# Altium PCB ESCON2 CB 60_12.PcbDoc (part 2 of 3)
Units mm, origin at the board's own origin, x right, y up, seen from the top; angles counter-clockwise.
Board outline 65.5 x 41 mm, 8 copper layers (Top Side, Mid Layer 1, Mid Layer 2, Mid Layer 3, Mid Layer 4, Mid Layer 5, Mid Layer 6, Bottom Side), stack 1.555 mm thick; 142 components, 77 nets, 455 pads, 2194 vias.
Unrouted connection lines stored in the file: 71.
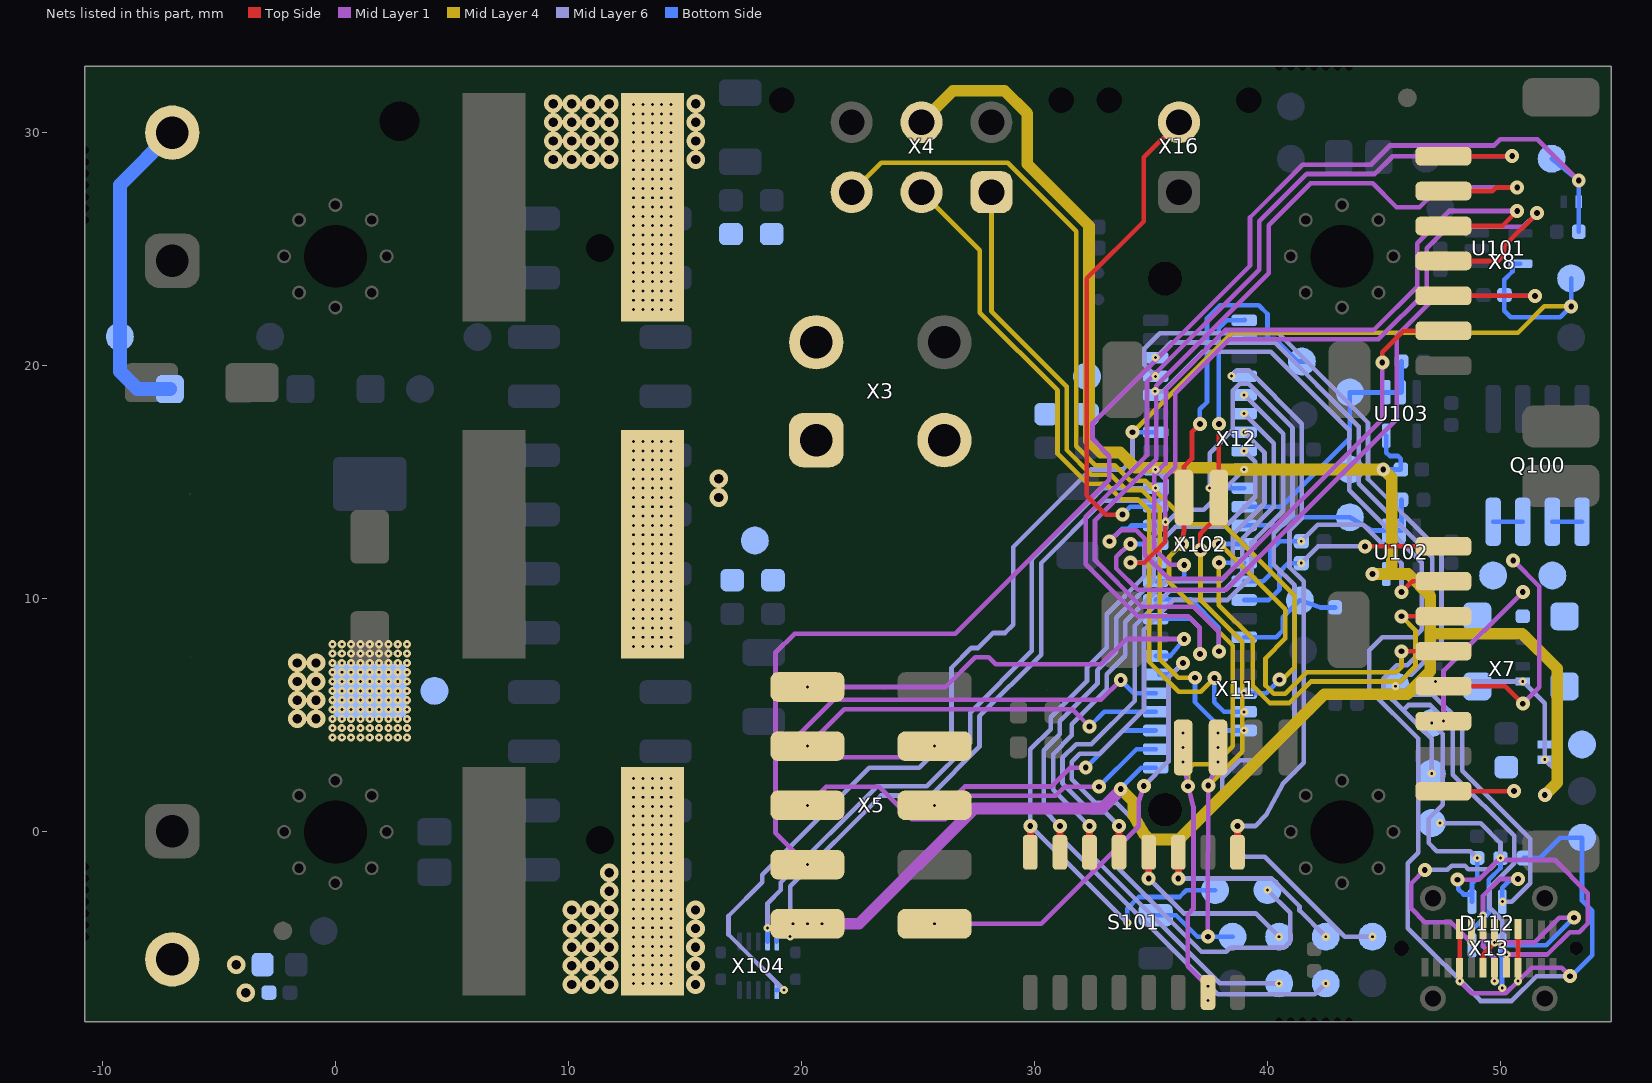
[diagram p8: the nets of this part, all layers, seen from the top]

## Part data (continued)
C112 C116 C122 C123 C124: library part CMP-001306-1, "100nF X7R >=50V 20%", Case=0402, Case (Metric)=1005, Dielectric=X7R, Manufacturer=X, Max Operating Temperature=125°C, Maximum Working Voltage=50V, Min Operating Temperature=-55°C, Part Number="Ceramic, 0402, 100nF, 20%, >{}50V, X7R, @, Soft Termination: N, -55°C to 125°C", Tolerance=20%
C113 C114 C115: library part CMP-001012-4, "220pF C0G/NP0/X7R >=100V 20%", Case=0603, Case (Metric)=1608, Dielectric=C0G/NP0/X7R, Manufacturer=X, Max Operating Temperature=125°C, Maximum Working Voltage=100V, Min Operating Temperature=-55°C, Part Number="Ceramic, 0603, 220pF, 20%, >{}100V, C0G/NP0/X7R, @, Soft Termination: N, -55°C to 125°C", Tolerance=20%
C119 C126: library part CMP-000703-3, "100nF X7R >=100V 20%", Case=0603, Case (Metric)=1608, Dielectric=X7R, Manufacturer=X, Max Operating Temperature=125°C, Maximum Working Voltage=100V, Min Operating Temperature=-55°C, Part Number="Ceramic, 0603, 100nF, 20%, >{}100V, X7R, @, Soft Termination: N, -55°C to 125°C", Tolerance=20%
C125: library part CMP-002520-1, "1nF C0G/NP0 >=100V 10%", Case=0402, Case (Metric)=1005, Dielectric=C0G/NP0, Max Operating Temperature=125°C, Maximum Working Voltage=100V, Min Operating Temperature=-55°C, Part Number="Ceramic, 0402, 1nF, 10%, >{}100V, C0G/NP0, @, Soft Termination: N, -55°C to 125°C", Tolerance=10%
D101 D104: library part CMP-001103-4, "Transient Voltage Suppressor Diode, 60V V(RWM), Unidirectional, 400W, 1 Element, DO-214AC", Breakdown Voltage=66.7V, Case=DO-214AC, Clamping Voltage=96.8V, Manufacturer=X, Max Operating Temperature=150°C, Min Operating Temperature=-55°C
D102 D103 D110 D111: library part CMP-000633-9, "Schottky Diode, >=90V, >=1A, SOD-123FL/SOD-123W", Case="Sub SMA; SOD-123FL", Manufacturer="Taiwan Semiconductor", Max Operating Temperature=150°C, Min Operating Temperature=-55°C, Reverse Voltage=90V, RMS Current=1A
D106: library part CMP-001106-5, "Transient Voltage Suppressor Diode, 12V V(RWM), Bidirectional, 100W, 1 Element, SOD-882/DFN1006", Breakdown Voltage=13V, Case="SOD-882; DFN1006", Manufacturer=Diodes, Max Operating Temperature=125°C, Min Operating Temperature=-40°C
D107 D108 D109: library part CMP-000606-13, "Diode Switching, >=70V, >=150mA, SOD882/DFN1006/0402/SOD-923F", Case="SOD882 / DFN1006 / 0402 / SOD-923F", Manufacturer=MCC, Max Operating Temperature=125°C, Min Operating Temperature=-40°C, Reverse Voltage=70V, RMS Current=150mA
D112: library part CMP-000635-10, "Transient Voltage Suppressor Diode, 4-Line, 5V V(RWM), Unidirectional, 30W, 4 Element , SOT353/SC-88A", Breakdown Voltage=6.8V, Case="SOT353; SC-88A; SOT323-5L", Clamping Voltage=12V, Manufacturer=Nexperia, Max Breakdown Voltage=7.14V, Max Junction Temperature=150°C, Min Breakdown Voltage=6.46V, Min Operating Temperature=-65°C
D113 D114: library part CMP-000066-17, "Transient Voltage Suppressor Diode, 30V V(RWM), Bidirectional, ESD, 1 Element, 0402", Breakdown Voltage=30V, Case=0402, Manufacturer=Panasonic, Max Operating Temperature=125°C, Min Operating Temperature=-55°C
DS101: library part CMP-000723-7, "Single Color Chip LED, red, 0603", Case=0603, Color(s)=Red, Manufacturer=Dialight, Max Operating Temperature=100°C, Min Operating Temperature=-40°C
DS102: library part CMP-000722-6, "Single Color Chip LED, green, 0603", Case=0603, Color(s)=Green, Manufacturer=Dialight, Max Operating Temperature=100°C, Min Operating Temperature=-40°C
F101: library part CMP-001206-4, "Electric Fuse, Very Fast Blow, 20A, 125VAC, 72VDC, 100A (IR), Surface Mount", Case=0456, Current Rating=20A, Max Operating Temperature=125°C, Maximum Working Voltage=72V, Min Operating Temperature=-55°C
FD101 FD102 FD103 FD104: library part CMP-000010-5, "Fiducial, Global, Round; 0.80 mm D, 1.60 mm Clearance"
L101 L102 L103: library part CMP-002153-3, "Inductor Shielded, 4.7uH, 20%, I_RMS>24.7A, I_Sat>21A, R<5.7mOhm, 11.0x11.9mm, Height<=10mm", DC Resistance=5.2, Max Operating Temperature=125°C, Min Operating Temperature=-55°C, RMS Current=24A, Saturation Current=21.4A, Tolerance=20%
LS101: library part CMP-001088-3, "Layer Stair 8 Layer"
MH101 MH102 MH103 MH104: library part CMP-000029-10, "Mounting Hole, Non-Plated; 5.50 mm Clearance, 2.70 mm Hole (with 8 vias)"
MH105: library part CMP-001003-6, "Mounting Hole, Non-Plated; 0.00 mm Clearance, 1.70 mm Hole"
Q100: library part CMP-001108-5, "N-Channel MOSFET, Self Protected, 36V, 0.5ohm, SO-8", Case="SO-8, SOIC-8, PG-DSO-8", Drain Source Voltage=36V, Manufacturer="ST Microelectronics", Max Operating Temperature=150°C, Min Operating Temperature=-55°C
R102 R103 R105: library part CMP-002605-3, "56R 5% 500mW 100ppm", Case=1206, Case (Metric)=3216, Max Junction Temperature=155°C, Maximum Overload Voltage=400V, Maximum Working Voltage=200V, Min Operating Temperature=-55°C, Part Number="Thick-Film, 1206, 56, 5%, 500mW@70°C, 200V, 100ppm, -55°C to 155°C", Power Rating=500mW, Power Rating Temperature=70°C, Temperature Coefficient=100ppm, Tolerance=5%
R104: library part CMP-000325-10, "120R 1% 125mW 100ppm", Case=0805, Case (Metric)=2012, Manufacturer=X, Max Junction Temperature=155°C, Maximum Overload Voltage=300V, Maximum Working Voltage=150V, Min Operating Temperature=-55°C, Part Number="Thick-Film, 0805, 120, 1%, 125mW@70°C, 150V, 100ppm, -55°C to 155°C", Power Rating=125mW, Power Rating Temperature=70°C, Temperature Coefficient=100ppm, Tolerance=1%
R107 R108: library part CMP-000206-11, "5.1k 1% 62.5mW 100ppm", Case=0402, Case (Metric)=1050, Manufacturer=X, Max Junction Temperature=155°C, Maximum Overload Voltage=100V, Maximum Working Voltage=50V, Min Operating Temperature=-55°C, Part Number="Thick-Film, 0402, 5.1k, 1%, 62.5mW@70°C, 50V, 100ppm, -55°C to 155°C", Power Rating=62.5mW, Power Rating Temperature=70°C, Temperature Coefficient=100ppm, Tolerance=1%
R109 R110: library part CMP-000185-11, "680R 1% 62.5mW 100ppm", Case=0402, Case (Metric)=1050, Manufacturer=X, Max Junction Temperature=155°C, Maximum Overload Voltage=100V, Maximum Working Voltage=50V, Min Operating Temperature=-55°C, Part Number="Thick-Film, 0402, 680, 1%, 62.5mW@70°C, 50V, 100ppm, -55°C to 155°C", Power Rating=62.5mW, Power Rating Temperature=70°C, Temperature Coefficient=100ppm, Tolerance=1%
R111: library part CMP-000161-11, "47R 1% 62.5mW 100ppm", Case=0402, Case (Metric)=1050, Manufacturer=X, Max Junction Temperature=155°C, Maximum Overload Voltage=100V, Maximum Working Voltage=50V, Min Operating Temperature=-55°C, Part Number="Thick-Film, 0402, 47, 1%, 62.5mW@70°C, 50V, 100ppm, -55°C to 155°C", Power Rating=62.5mW, Power Rating Temperature=70°C, Temperature Coefficient=100ppm, Tolerance=1%
R112 R114: library part CMP-000173-11, "220R 1% 62.5mW 100ppm", Case=0402, Case (Metric)=1050, Manufacturer=X, Max Junction Temperature=155°C, Maximum Overload Voltage=100V, Maximum Working Voltage=50V, Min Operating Temperature=-55°C, Part Number="Thick-Film, 0402, 220, 1%, 62.5mW@70°C, 50V, 100ppm, -55°C to 155°C", Power Rating=62.5mW, Power Rating Temperature=70°C, Temperature Coefficient=100ppm, Tolerance=1%
R115 R116: library part CMP-000197-11, "2.2k 1% 62.5mW 100ppm", Case=0402, Case (Metric)=1050, Manufacturer=X, Max Junction Temperature=155°C, Maximum Overload Voltage=100V, Maximum Working Voltage=50V, Min Operating Temperature=-55°C, Part Number="Thick-Film, 0402, 2.2k, 1%, 62.5mW@70°C, 50V, 100ppm, -55°C to 155°C", Power Rating=62.5mW, Power Rating Temperature=70°C, Temperature Coefficient=100ppm, Tolerance=1%
R117: library part CMP-000466-10, "0R Jumper", Case=0402, Case (Metric)=1050, Manufacturer=X, Max Junction Temperature=155°C, Maximum Overload Voltage=100V, Maximum Working Voltage=50V, Min Operating Temperature=-55°C, Part Number="Thick-Film, 0402, 0, -55°C to 155°C", RMS Current=1A
R118 R119 R120 R121: library part CMP-000492-11, "10k 1% 62.5mW 100ppm", Case=0402, Case (Metric)=1050, Manufacturer=X, Max Junction Temperature=155°C, Maximum Overload Voltage=100V, Maximum Working Voltage=50V, Min Operating Temperature=-55°C, Part Number="Thick-Film, 0402, 10k, 1%, 62.5mW@70°C, 50V, 100ppm, -55°C to 155°C", Power Rating=62.5mW, Power Rating Temperature=70°C, Temperature Coefficient=100ppm, Tolerance=1%
S101: library part CMP-001031-4, "Slide Dip Switch, 8 Switches, 0.025A, 24VDC, SMD", Case=-, Manufacturer=Diptronics, Max Operating Temperature=85°C, Min Operating Temperature=-40°C
STEG101 STEG102 STEG103 STEG104: library part CMP-002391-3, "Breakaway tabs; 5.70 mm L X 0.90 mm W, 7 Hole, Bear-Ears, Preferred"
SYM101: library part CMP-001187-11, "Barcode EMS; 4.1 x 4.1 mm"
SYM103: library part CMP-000018-6, "ESD-Sign; 5.0 mm L X 4.5 mm W"
SYM104: library part CMP-001914-3, "PCB Marking UL Manufacturer; 8.8 x 1.7 mm"
SYM105: library part CMP-001916-4, "PCB Marking Flammability; 6.7 x 1.7 mm"
SYM106: library part CMP-001912-2, "PCB Marking Date; 5.0 x 1.5 mm"
TP101 TP102 TP103 TP104 TP106 TP107 TP108 TP109 TP110 TP111 TP112 TP113 TP114 TP115 TP116 TP117 TP118 TP119 TP120 TP121 TP125 TP126 TP127 TP128 TP129 TP130 TP131 TP132 TP133 TP134 TP138 TP139 TP140 TP141 TP142 TP143 TP144 TP145 TP146 TP147 TP148 TP149 TP153 TP154 TP155: library part CMP-000014-7, "Test Point; 1 pin, 1.20 mm D"
TPM101 TPM102: library part CMP-001150-4, "Test point measure; 1 pin, 0.50 mm D"
U101: library part CMP-001041-6, "Single buffer with Schmitt-Trigger inputs", Case="5-TSSOP, SC-70-5, SOT-353", Manufacturer="Texas Instruments", Max Operating Temperature=125°C, Max Storage Temperature=150°C, Max Supply Voltage=5.5V, Min Operating Temperature=-40°C, Min Storage Temperature=-65°C, Min Supply Voltage=1.65V
U102 U103: library part CMP-002037-1, "Single, 2-Input NAND Gate, 5V", Case="SC-88A , SC-70-5, SOT353-1", Max Operating Temperature=125°C, Max Supply Voltage=5.5V, Min Operating Temperature=-40°C, Min Supply Voltage=4.5V
X1 X2: library part CMP-001528-6, "Mini-Fit Plus Header, Dual Row, Vertical, 2 Circuits, without Snap-in Plastic Peg PCB Lock, without Drain Holes, PA Polyamide Nylon 6/6, UL 94V-0, Tin (Sn) 1.27µm Over Nickel (Ni) Plating", Max Operating Temperature=105°C, Min Operating Temperature=-40°C, Operating Current=13A, Operating Voltage=600V
X3: library part CMP-001529-10, "Mini-Fit Plus Header, Dual Row, Vertical, 4 Circuits, without Snap-in Plastic Peg PCB Lock, without Drain Holes, PA Polyamide Nylon 6/6, UL 94V-0, Tin (Sn) 1.27µm Over Nickel (Ni) Plating", Max Operating Temperature=105°C, Min Operating Temperature=-40°C, Operating Current=13A, Operating Voltage=600V
X4: library part CMP-001098-6, "Micro-Fit 3.0 Vertical Header, 3.00mm Pitch, Dual Row, 6 Circuits, with PCB Polarizing Peg, Black", Manufacturer=Molex, Max Operating Temperature=105°C, Min Operating Temperature=-40°C, Operating Current=8.5A, Operating Voltage=600V
X5: library part CMP-001165-4, "Header, 2.54mm Pitch, Dual Row, SMT, Vertical, 10 Circuits", Max Operating Temperature=125°C, Min Operating Temperature=-65°C, Operating Current=3A, Operating Voltage=500V
X7: library part CMP-001014-7, "1.50mm Pitch, CLIK-Mate PCB Receptacle, Single Row, Surface Mount, Tin Plating, Positive Lock, with Pick-and-Place Polyimide Tape, 8 Circuits, Beige", Manufacturer=Molex, Max Operating Temperature=105°C, Min Operating Temperature=-40°C, Operating Current=2A, Operating Voltage=100V
X8: library part CMP-001015-7, "1.50mm Pitch, CLIK-Mate PCB Receptacle, Single Row, Surface Mount, Tin Plating, Positive Lock, with Pick-and-Place Polyimide Tape, 7 Circuits, Beige", Manufacturer=Molex, Max Operating Temperature=105°C, Min Operating Temperature=-40°C, Operating Current=2A, Operating Voltage=100V
X11 X12: library part CMP-001170-6, "1.50mm Pitch, CLIK-Mate PCB Receptacle, Single Row, Surface Mount, Tin Plating, Positive Lock, with Pick-and-Place Polyimide Tape, 4 Circuits, Beige", Manufacturer=Molex, Max Operating Temperature=105°C, Min Operating Temperature=-40°C, Operating Current=2A, Operating Voltage=100V
X13: library part CMP-001110-10, "USB Type C, SHLD, 24poles, vertical", Manufacturer=GTC, Max Operating Temperature=85°C, Min Operating Temperature=-25°C
X16: library part CMP-001107-4, "Micro-Fit 3.0 Vertical Header, 3.00mm Pitch, Dual Row, 2 Circuits, with PCB Polarizing Peg, Black", Manufacturer=Molex, Max Operating Temperature=105°C, Min Operating Temperature=-40°C, Operating Current=8.5A, Operating Voltage=600V
X101: library part CMP-002080-5, "Surface Mount PCB Socket Strips, 2.54mm pitch, 24 Circuits", Manufacturer=Samtec, Max Operating Temperature=125°C, Min Operating Temperature=-55°C, Operating Current=3A, Operating Voltage=405V
X102: library part CMP-002077-3, "RECT CONN BOARD Header, Center Strip Contacts 50 POS 0.8mm Gold", Max Operating Temperature=125°C, Min Operating Temperature=-55°C, Operating Current=1.4A, Operating Voltage=225V
X104: library part CMP-001083-11, "Board to Board Connector, 2*5 pole, SMD, 0.4mm pitch, 1.5mm stacking Height", Manufacturer=Panasonic, Max Operating Temperature=85°C, Min Operating Temperature=-55°C, Operating Current=300mA, Operating Voltage=60V

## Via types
v1: diameter 0.35, hole 0.125, Mid Layer 6 to Bottom Side, tented both sides, 1058 vias
v2: diameter 0.35, hole 0.125, Top Side to Mid Layer 1, tented both sides, 820 vias
v3: diameter 0.8, hole 0.4, Top Side to Bottom Side, 205 vias
v4: diameter 0.6, hole 0.25, Top Side to Bottom Side, 111 vias

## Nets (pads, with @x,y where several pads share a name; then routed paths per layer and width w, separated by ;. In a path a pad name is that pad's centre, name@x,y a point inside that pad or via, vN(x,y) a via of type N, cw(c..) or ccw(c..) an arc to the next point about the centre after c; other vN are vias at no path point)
3V3: C116.2 TP148.1 U101.5 X102.38 X104.1 | length 63.8
  Mid Layer 6 w0.2: v1(19.245,-6.78) 16.87,-4.405 16.87,-3.61 18.318,-2.163 18.318,-1.842 22.916,2.757 25.053,2.757 26.44,4.144 26.44,7.038 27.294,7.892 27.592,7.892 28.236,8.536 28.734,8.536 29.086,8.887 29.086,12.224 32.412,15.55 33.798,15.55 34.209,15.961 v4(34.209,17.15)
  Mid Layer 4 w0.2: v4(34.209,17.15) 38.485,21.425 50.751,21.425 51.876,22.55 v4(53.032,22.55)
  Bottom Side w0.2: X104.1@18.945,-6.795 18.945,-6.78 v1(19.245,-6.78) ; v4(34.209,17.15) X102.38@35.2,17.15 ; U101.5@50.852,24.386 50.599,24.386 50.514,24.301 50.514,24.048 50.167,23.701 C116.2@50.167,23.036 50.167,22.359 50.447,22.08 52.561,22.08 v4(53.032,22.55) TP148.1@53.032,23.75
5V0_sensor1_2: C122.2 D107.2 D108.2 D109.2 TP147.1 U102.5 U103.5 X4.5 X5.2 X102.2 | length 106.4
  Mid Layer 1 w0.5: v2(19.634,-3.943) v2(20.257,-3.943) v2(20.879,-3.943) 22.471,-3.943 27.414,1 32.89,1 33.703,1.813 v4(33.703,1.838)
  Mid Layer 6 w0.2: v1(47.205,6.455) v1(50.955,6.455) 51.9,5.51 v1(51.9,3.1) 52.428,2.572 52.428,2.105 v4(51.9,1.577)
  Mid Layer 4 w0.5: X4.5@25.154,30.453 26.504,31.803 28.713,31.803 29.686,30.83 29.686,28.66 32.342,26.003 32.342,16.78 32.84,16.282 33.674,16.282 34.333,15.623 37.688,15.623 37.762,15.55 v4(44.968,15.55) 45.326,15.192 45.326,11.065 ; v4(33.703,1.838) 34.25,1.291 34.25,0.697 34.729,-0.125 34.929,-0.325 36.209,-0.325 42.434,5.899 45.999,5.899 46.987,6.886 46.987,8.5 ; v4(44.5,11.065) 46.035,11.065 46.987,10.113 46.987,8.5 ; v4(51.9,1.577) 52.428,2.105 52.428,7.012 50.94,8.5 46.987,8.5
  Bottom Side w0.2: v4(33.703,1.838) 33.703,1.877 34.576,2.75 X102.2@35.2,2.75 ; TP147.1@43.533,15.55 v4(44.968,15.55) ; v4@44.978,15.56 v4(44.968,15.55) ; U103.5@45.1,17 45.1,16.277 45.246,16.131 45.597,16.131 45.725,16.003 C122.2@45.725,15.55 v4(44.968,15.55)
  Bottom Side w0.3: v4(44.5,11.065) U102.5@45.1,11.065
C_ADC_CB_Ident: R118.2 TP143.1 X102.15 | length 4.9
  Bottom Side w0.2: X102.15@39,8.35 40.369,8.35 40.66,8.641 40.66,9.201 TP143.1@41.39,9.931 42.259,9.631 R118.2@42.902,9.631
C_AnIN1+: X8.1 X102.18 | length 43.1
  Top Side w0.2: X8.1@47.55,29 v4(50.5,29)
  Mid Layer 1 w0.2: v4(37.1,7.633) 37.1,8.75 36.592,9.258 34.428,9.258 32.201,11.484 32.201,13.533 34.831,16.163 34.831,19.312 39.65,24.131 39.65,24.168 39.65,26.199 41.662,28.211 41.682,28.231 44.599,28.231 45.368,29 v4(50.5,29)
  Bottom Side w0.2: X102.18@35.2,9.15 36.7,9.15 37.1,8.75 v4(37.1,7.633)
C_AnIN1-: X8.2 X102.20 | length 44.5
  Top Side w0.2: X8.2@47.55,27.5 49.644,27.5 49.794,27.65 v4(50.717,27.65)
  Mid Layer 1 w0.2: v4(37.915,7.75) 37.915,8.584 36.842,9.658 34.593,9.658 32.601,11.65 32.601,13.368 35.231,15.997 35.231,19.146 40.05,23.966 40.05,24.003 40.05,26.033 41.847,27.831 44.511,27.831 45.535,26.807 46.523,26.807 47.366,27.65 v4(50.717,27.65)
  Bottom Side w0.2: X102.20@35.2,9.95 35.231,9.981 36.7,9.981 37.915,8.766 v4(37.915,7.75)
C_AnIN2+: X8.3 X102.22 | length 33.2
  Top Side w0.2: X8.3@47.55,26 50.072,26 v4(50.717,26.645)
  Mid Layer 1 w0.2: v4(36.425,11.458) 35.836,11.458 35.14,12.155 35.14,15.326 35.62,15.807 35.62,15.821 35.631,15.831 35.631,18.981 38.187,21.537 44.566,21.537 46.421,23.392 46.421,25.265 47.801,26.645 v4(50.717,26.645)
  Bottom Side w0.2: X102.22@35.2,10.75 36.229,10.75 36.425,10.946 v4(36.425,11.458)
C_AnIN2-: X8.4 X102.24 | length 34.4
  Top Side w0.2: v4(34.115,11.55) 34.71,11.55 34.885,11.725 35.618,12.458 v2(35.618,13.306) ; X8.4@47.55,24.5 49.903,24.5 50.166,24.763 50.166,25.15 v4(51.572,26.556)
  Mid Layer 1 w0.2: v4@34.115,11.527 v4(34.115,11.55) ; v2(35.618,13.306) 35.618,15.215 36.044,15.641 36.044,18.828 38.353,21.137 44.762,21.137 46.832,23.207 46.832,25.045 47.756,25.969 50.985,25.969 v4(51.572,26.556)
  Bottom Side w0.2: v4(34.115,11.55) X102.24@35.2,11.55
C_AnOUT1: X8.5 X102.26 | length 32
  Top Side w0.2: X8.5@47.55,23 v4(51.477,23)
  Mid Layer 1 w0.2: v4(34.115,12.35) 34.067,12.35 33.515,11.799 33.515,11.301 34.428,10.389 38.229,10.389 45.552,17.712 45.552,21.297 47.255,23 v4(51.477,23)
  Bottom Side w0.2: v4(34.115,12.35) X102.26@35.2,12.35
C_AnOUT2: X8.6 X102.28 | length 24.2
  Top Side w0.2: v4(44.927,20.145) 44.927,20.586 45.841,21.5 X8.6@47.55,21.5
  Mid Layer 1 w0.2: v4(33.215,12.47) 33.695,12.95 34.364,12.95 34.727,12.586 34.727,11.894 35.763,10.858 38.086,10.858 44.927,17.699 v4@44.927,20.046 ; v4(44.927,20.145) v4@45.027,20.046
  Bottom Side w0.2: v4(33.215,12.47) 33.759,13.013 34.028,13.013 34.164,13.15 X102.28@35.2,13.15
C_CANH: S101.7 TP114.1 X11.1 X12.1 X102.47 | length 42.3
  Top Side w0.2: v4(36.327,12.345) 36.415,12.927 X12.1@36.415,14.35 36.415,15.66 36.758,16.002 36.758,17.157 v4(37.1,17.5)
  Mid Layer 1 w0.2: v2(36.379,4.247) v2(36.379,3.625) v2(36.379,3.002) v4(36.594,1.958) 36.822,1.067 36.822,-3.307 36.574,-3.555 36.574,-5.759 v2(37.442,-6.627) v2(37.442,-7.237)
  Mid Layer 4 w0.2: v4(36.327,12.345) 35.772,11.791 35.772,10.741 38.515,7.998 38.515,3.671 37.744,2.899 36.825,2.899 36.594,2.669 v4(36.594,1.958)
  Bottom Side w0.2: v4(37.1,17.5) 37.1,18.141 37.407,18.447 37.407,22.033 37.967,22.593 39.629,22.593 40,22.223 40,21.15 ; X102.47@39,21.15 40,21.15 ; TP114.1@41.65,20.185 41.3,20.185 40.335,21.15 40,21.15
C_CANL: R104.2 TP115.1 X11.2 X12.2 X102.49 | length 35.1
  Top Side w0.2: v4(37.123,12.094) 37.123,12.798 37.915,13.59 v4(37.915,17.5)
  Mid Layer 1 w0.2: v4(37.442,-4.5) 37.442,-0.904 37.459,-0.886 v4(37.459,1.986) v2(37.879,3.002) v2(37.879,3.625) v2(37.879,4.247)
  Mid Layer 4 w0.2: v4(37.123,12.094) 37.123,9.956 38.915,8.164 38.915,3.442 v4(37.459,1.986)
  Bottom Side w0.2: R104.2@35.2,-3.575 36.075,-3.575 36.997,-4.497 37.438,-4.497 v4(37.442,-4.5) TP115.1@38.5,-4.5 ; v4(37.915,17.5) 37.915,21.615 38.25,21.95 X102.49@39,21.95 X102.49@39.015,21.965
C_DigIN1: D113.2 X7.1 X102.19 | length 9.9
  Top Side w0.2: v4(44.179,12.25) X7.1@47.55,12.25
  Mid Layer 6 w0.2: v1(41.45,11.53) 42.17,12.25 v4(44.179,12.25)
  Bottom Side w0.2: X102.19@39,9.95 40.054,9.95 40.518,10.413 40.518,11.167 40.88,11.53 v1(41.45,11.53)
C_DigIN2: D114.2 X7.2 X102.21 | length 12.3
  Top Side w0.2: v4(45.75,10.289) 46.211,10.75 X7.2@47.55,10.75
  Mid Layer 6 w0.2: v1(41.45,12.47) 42.153,13.173 44.104,13.173 45.75,11.528 v4(45.75,10.289)
  Bottom Side w0.2: X102.21@39,10.75 39.809,10.75 40.115,11.056 40.115,12.061 40.524,12.47 v1(41.45,12.47)
C_DigIN3: X7.3 X102.23 | length 19.1
  Top Side w0.2: v4(45.75,9.25) X7.3@47.55,9.25
  Mid Layer 4 w0.2: v4(37.915,11.55) 37.915,9.729 39.365,8.279 39.365,6.268 40.104,5.53 40.932,5.53 41.851,6.449 45.696,6.449 46.35,7.103 46.35,8.65 v4(45.75,9.25)
  Bottom Side w0.2: v4(37.915,11.55) X102.23@39,11.55
C_DigIN4: X7.4 X102.25 | length 17.6
  Top Side w0.2: v4(45.75,7.75) X7.4@47.55,7.75
  Mid Layer 4 w0.2: v4(37.915,12.35) 37.964,12.35 40.766,9.548 40.766,8.3 39.918,7.451 39.918,6.281 40.269,5.93 40.766,5.93 41.685,6.849 45.531,6.849 45.75,7.069 v4(45.75,7.75)
  Bottom Side w0.2: v4(37.915,12.35) X102.25@39,12.35
C_DigOUT1: D110.2 Q100.7 Q100.8 R115.1 TP111.1 X7.5 | length 11.9
  Top Side w0.2: X7.5@47.55,6.25 50.205,6.25 v4(50.955,5.5)
  Mid Layer 1 w0.2: v4(50.545,11.65) 51.665,10.53 51.665,6.21 v4(50.955,5.5)
  Bottom Side w0.2: Q100.8@49.685,13.308 Q100.7@50.955,13.308
C_DigOUT2: D111.2 Q100.5 Q100.6 R116.1 TP112.1 X7.6 | length 8.2
  Mid Layer 1 w0.2: v2(47.55,4.75) 47.55,6.884 v4(50.955,10.289)
  Bottom Side w0.2: Q100.6@52.225,13.308 Q100.5@53.495,13.308
C_MotorTemp: X16.2 X102.30 | length 21.1
  Top Side w0.2: v4(33.779,13.613) 33.063,13.613 32.25,14.426 32.25,23.75 34.692,26.192 34.692,28.942 X16.2@36.202,30.453
  Bottom Side w0.2: v4(33.779,13.613) 34.116,13.95 X102.30@35.2,13.95
C_S1_Hall1: X4.1 X102.5 | length 29.4
  Mid Layer 4 w0.2: X4.1@28.154,27.453 28.154,22.348 31.392,19.11 31.392,16.386 32.446,15.332 33.28,15.332 33.939,14.673 34.593,14.673 35.324,13.942 35.324,13.928 35.372,13.88 35.372,7.406 36.165,6.613 v4(36.89,6.613)
  Bottom Side w0.2: v4(36.89,6.613) 36.89,5.556 38.096,4.35 v1(39,4.35)
C_S1_Hall2: X4.2 X102.7 | length 31.1
  Mid Layer 4 w0.2: X4.2@25.154,27.453 27.655,24.952 27.655,22.281 30.992,18.944 30.992,16.221 32.281,14.932 33.06,14.932 33.719,14.273 34.428,14.273 34.924,13.776 34.924,7.288 36.199,6.013 37.139,6.013 37.719,6.594 v4(37.719,6.6)
  Bottom Side w0.2: v4(37.719,6.6) 37.719,5.564 38.133,5.15 v1(39,5.15)
C_S1_Hall3: X4.3 X102.9 | length 38.3
  Mid Layer 4 w0.2: X4.3@22.154,27.453 23.422,28.72 28.847,28.72 31.792,25.776 31.792,16.552 32.612,15.732 33.446,15.732 34.105,15.073 34.759,15.073 36.638,13.194 38.103,13.194 41.166,10.131 41.166,7.07 40.626,6.53 v4(40.518,6.53)
  Bottom Side w0.2: v1(39,5.95) 39.938,5.95 v4(40.518,6.53)
C_S2_/A: X5.5 X102.6 | length 10.8
  Mid Layer 1 w0.2: v2(25.717,1.137) 26.208,1.137 27.021,1.95 30.737,1.95 31.544,2.757 v4(32.201,2.757)
  Bottom Side w0.2: v4(32.201,2.757) 33.794,4.35 X102.6@35.2,4.35
C_S2_/B: X5.7 X102.10 | length 23.5
  Mid Layer 1 w0.2: v2(25.717,3.677) 25.242,3.202 20.06,3.202 19.733,3.529 19.733,4.02 21.378,5.665 32.855,5.665 v4(33.703,6.513)
  Bottom Side w0.2: v4(33.703,6.513) 34.266,5.95 X102.10@35.2,5.95
C_S2_A_HsDgin1: X5.6 X102.4 | length 17.1
  Mid Layer 1 w0.2: v2(20.257,1.137) 21.057,1.938 23.332,1.938 24.728,0.541 26.177,0.541 27.186,1.55 30.903,1.55 31.29,1.938 v4(32.767,1.938)
  Bottom Side w0.2: v4(32.767,1.938) 34.38,3.55 X102.4@35.2,3.55
C_S2_B_HsDgin2: X5.8 X102.8 | length 16.2
  Mid Layer 1 w0.2: v2(20.257,3.677) 21.845,5.265 31.619,5.265 v4(32.362,4.522)
  Bottom Side w0.2: v4(32.362,4.522) 32.99,5.15 X102.8@35.2,5.15
C_S2_Clock_HsDgout1: D106.2 R111.1 TP110.1 X5.4 | length 61.3
  Mid Layer 1 w0.2: v2(20.257,-1.403) 18.885,-0.032 18.885,7.684 19.704,8.503 26.605,8.503 33.215,15.113 33.215,16.119 32.492,16.842 32.492,17.539 39.25,24.297 39.25,26.365 41.498,28.613 41.516,28.631 44.433,28.631 45.26,29.458 49.726,29.458 49.992,29.724 51.584,29.724 v4(53.357,27.95)
  Bottom Side w0.2: TP110.1@52.194,28.885 v4(53.357,27.95) D106.2@53.357,27.036 R111.1@53.357,25.756
C_S2_Data_HsDgin4: X5.1 X102.12 | length 19.5
  Mid Layer 1 w0.2: v2(25.717,-3.943) 30.287,-3.943 34.475,0.245 34.475,1.308 34.643,1.816 v4(34.693,1.965)
  Mid Layer 6 w0.2: v4(34.693,1.965) 35.75,3.022 35.75,6.623 v4(36.377,7.25)
  Bottom Side w0.2: X102.12@35.357,6.75 35.877,6.75 v4(36.377,7.25)
C_S2_I_HsDgin3: X5.10 X102.14 | length 18.9
  Mid Layer 1 w0.2: v2(20.257,6.217) 26.185,6.217 27.46,7.492 28.04,7.492 28.344,7.188 32.853,7.188 33.938,8.273 v4(36.425,8.273)
  Bottom Side w0.2: X102.14@35.2,7.55 35.828,7.55 v4(36.425,8.273) v4@36.349,8.197
C_USB_CC1: D112.3 R107.1 TP118.1 X13.A5 | length 17.1
  Top Side w0.2: v2(48.75,-4.75) X13.A5@48.75,-4.165
  Mid Layer 1 w0.2: v4(46.75,-1.632) 46.166,-2.216 46.166,-3.285 46.756,-3.874 47.874,-3.874 v2(48.75,-4.75)
  Mid Layer 6 w0.2: v4(46.75,-1.632) 47.723,-1.632 47.902,-1.453 48.476,-1.453 48.622,-1.599 49.529,-1.599 v1(50,-1.128) 50,-0.481 49.143,0.376 v1(47.4,0.376)
  Bottom Side w0.2: D112.3@48.779,-4.867 48.779,-4.207 49.5,-3.485 49.5,-2.05 50,-1.55 v1(50,-1.128)
C_USB_CC2: D112.4 R108.1 TP121.1 X13.B5 | length 23.5
  Top Side w0.2: X13.B5@50.25,-5.835 v2(50.25,-5.263)
  Mid Layer 1 w0.2: v4(48.15,-2.053) 49.061,-2.053 49.91,-1.204 52.322,-1.204 53.75,-2.632 53.75,-3.932 53.372,-4.31 52.964,-4.31 52.012,-5.263 v2(50.25,-5.263)
  Mid Layer 6 w0.2: v1(47.05,4.675) 47.525,4.2 47.525,1.173 46.925,0.573 46.925,-0.479 47.273,-0.826 48.702,-0.826 v1(49,-1.124)
  Bottom Side w0.2: v4(48.15,-2.053) 48.191,-2.094 48.191,-2.461 48.414,-2.685 48.694,-2.685 D112.4@48.779,-2.77 ; D112.4@48.779,-2.997 D112.4@48.779,-2.77 ; v1(49,-1.124) 49,-1.979 48.779,-2.2 D112.4@48.779,-2.77
C_USB_D+: D112.5 TP119.1 X13.A6 X13.B6 X102.44 | length 47.7
  Top Side w0.2: X13.A6@49.249,-4.164 v2(49.249,-3.593) ; v2(49.75,-6.407) X13.B6@49.75,-5.835
  Mid Layer 1 w0.2: v2(49.75,-6.407) 49.75,-5.422 49.249,-4.921 v2(49.249,-3.593) 49.249,-2.75 49.974,-2.026 v4(50.75,-2.026)
  Mid Layer 6 w0.2: v1(35.2,19.55) 34.705,20.045 34.705,20.735 35.371,21.4 40.472,21.4 44.314,17.558 44.314,15.142 47.47,11.986 47.47,8.056 46.164,6.75 46,6.75 v1(45.5,6.25) 45.857,5.893 47.095,5.893 48.352,4.636 48.352,2.626 51.27,-0.292 51.27,-2.207 50.481,-2.997 v1(50.079,-2.997)
  Bottom Side w0.2: v1(50.079,-2.997) 50.079,-2.398 50.376,-2.1 50.675,-2.1 v4(50.75,-2.026)
C_USB_D-: D112.1 TP120.1 X13.A7 X13.B7 X102.46 | length 53.5
  Top Side w0.2: X13.B7@49.25,-5.835 49.25,-5.25 v2(49.75,-4.75) X13.A7@49.75,-4.165
  Mid Layer 1 w0.2: v2(49.75,-4.75) 51.45,-4.75 52.517,-3.683 v4(53.15,-3.683)
  Mid Layer 6 w0.2: v1(35.2,20.35) 35.85,21 40.306,21 43.914,17.392 43.914,14.932 47.07,11.775 47.07,8.221 45.999,7.15 45.553,7.15 44.976,6.573 44.976,6.061 45.818,5.219 ; v1(47.05,2.5) 47.05,3.987 45.818,5.219 ; v1(50.079,-4.867) 50.079,-3.8 49.529,-3.251 49.529,-2.398 50.586,-1.341 50.586,-0.174 47.952,2.46 47.952,4.471 46.98,5.443 46.041,5.443 45.818,5.219
  Bottom Side w0.2: v1(50.075,-6.704) 50.065,-6.693 50.065,-4.881 v1(50.079,-4.867) 51.966,-4.867 v4(53.15,-3.683)
C_USB_VBUS: C112.2 TP117.1 X13.A4 X13.A9 X13.B4 X13.B9 X102.42 | length 64
  Top Side w0.2: v2(48.25,-6.407) X13.B9@48.25,-5.835 X13.A4@48.25,-4.165 ; v2(50.75,-6.407) X13.B4@50.75,-5.835 X13.A9@50.75,-4.165
  Mid Layer 1 w0.2: v2(48.25,-6.407) 48.772,-6.93 50.228,-6.93 v2(50.75,-6.407) 51.331,-5.826 52.618,-5.826 v4(52.987,-6.195)
  Mid Layer 6 w0.2: v1(35.18,18.907) 35.52,18.907 37.214,20.6 40.14,20.6 43.514,17.227 43.514,14.668 46.625,11.557 46.625,8.671 46.304,8.35 44.919,8.35 44.368,7.799 44.368,6.103 46.465,4.005 46.465,-0.899 46.02,-1.345 46.02,-4.132 49.143,-7.255 50.483,-7.255 51.543,-6.195 v4(52.987,-6.195)
  Bottom Side w0.2: C112.2@51,-1.124 51.69,-1.124 52.564,-0.25 TP117.1@53.5,-0.25 53.5,-2.952 53.94,-3.392 53.94,-5.286 53.031,-6.195 v4(52.987,-6.195)
C_VDigIO: C119.2 D107.1 D110.1 D111.1 TP113.1 X7.8 | length 3
  Top Side w0.2: X7.8@47.55,1.75 v4(50.578,1.75)
C_VL: D102.2 TP102.1 X2.2 | length 13.6
  Bottom Side w0.6: D102.2@-7.102,19 -8.5,19 -9.25,19.75 -9.25,27.756 X2.2@-7,30.006
C_VP: C125.2 C126.1 F101.1 TP103.1 X1.2
  other v1: -0.124,4.05 0.276,4.05 0.676,4.05 1.076,4.05 1.476,4.05 1.876,4.05 2.276,4.05 2.676,4.05 3.076,4.05 -0.124,4.45 0.276,4.45 0.676,4.45 1.076,4.45 1.476,4.45 1.876,4.45 2.276,4.45 2.676,4.45 3.076,4.45 -0.124,4.85 0.276,4.85 0.676,4.85 1.076,4.85 1.476,4.85 1.876,4.85 2.276,4.85 2.676,4.85 3.076,4.85 -0.124,5.25 0.276,5.25 0.676,5.25 1.076,5.25 1.476,5.25 1.876,5.25 2.276,5.25 2.676,5.25 3.076,5.25 -0.124,5.65 0.276,5.65 0.676,5.65 1.076,5.65 1.476,5.65 1.876,5.65 2.276,5.65 2.676,5.65 3.076,5.65 -0.124,6.05 0.276,6.05 0.676,6.05 1.076,6.05 1.476,6.05 1.876,6.05 2.276,6.05 2.676,6.05 3.076,6.05 -0.124,6.45 0.276,6.45 0.676,6.45 1.076,6.45 1.476,6.45 1.876,6.45 2.276,6.45 2.676,6.45 3.076,6.45 -0.124,6.85 0.276,6.85 0.676,6.85 1.076,6.85 1.476,6.85 1.876,6.85 2.276,6.85 2.676,6.85 3.076,6.85 -0.124,7.25 0.276,7.25 0.676,7.25 1.076,7.25 1.476,7.25 1.876,7.25 2.276,7.25 2.676,7.25 3.076,7.25 -0.124,7.65 0.276,7.65 0.676,7.65 1.076,7.65 1.476,7.65 1.876,7.65 2.276,7.65 2.676,7.65 3.076,7.65 -0.124,8.05 0.276,8.05 0.676,8.05 1.076,8.05 1.476,8.05 1.876,8.05 2.276,8.05 2.676,8.05 3.076,8.05
  other v3: -3.85,-6.9 -4.25,-5.7 -1.634,4.85 -0.834,4.85 -1.634,5.65 -0.834,5.65 -1.634,6.45 -0.834,6.45 -1.634,7.25 -0.834,7.25
C_W1: C107.2 C113.2 L101.1 TP107.1 X3.1
  other v2: 12.802,22.413 13.202,22.413 13.602,22.413 14.002,22.413 14.402,22.413 12.802,22.813 13.202,22.813 13.602,22.813 14.002,22.813 14.402,22.813 12.802,23.213 13.202,23.213 13.602,23.213 14.002,23.213 14.402,23.213 12.802,23.613 13.202,23.613 13.602,23.613 14.002,23.613 14.402,23.613 12.802,24.013 13.202,24.013 13.602,24.013 14.002,24.013 14.402,24.013 12.802,24.413 13.202,24.413 13.602,24.413 14.002,24.413 14.402,24.413 12.802,24.813 13.202,24.813 13.602,24.813 14.002,24.813 14.402,24.813 12.802,25.213 13.202,25.213 13.602,25.213 14.002,25.213 14.402,25.213 12.802,25.613 13.202,25.613 13.602,25.613 14.002,25.613 14.402,25.613 12.802,26.013 13.202,26.013 13.602,26.013 14.002,26.013 14.402,26.013 12.802,26.413 13.202,26.413 13.602,26.413 14.002,26.413 14.402,26.413 12.802,26.813 13.202,26.813 13.602,26.813 14.002,26.813 14.402,26.813 12.802,27.213 13.202,27.213 13.602,27.213 14.002,27.213 14.402,27.213 12.802,27.613 13.202,27.613 13.602,27.613 14.002,27.613 14.402,27.613 12.802,28.013 13.202,28.013 13.602,28.013 14.002,28.013 14.402,28.013 12.802,28.413 13.202,28.413 13.602,28.413 14.002,28.413 14.402,28.413 12.802,28.813 13.202,28.813 13.602,28.813 14.002,28.813 14.402,28.813 12.802,29.213 13.202,29.213 13.602,29.213 14.002,29.213 14.402,29.213 12.802,29.613 13.202,29.613 13.602,29.613 14.002,29.613 14.402,29.613 12.802,30.013 13.202,30.013 13.602,30.013 14.002,30.013 14.402,30.013 12.802,30.413 13.202,30.413 13.602,30.413 14.002,30.413 14.402,30.413 12.802,30.813 13.202,30.813 13.602,30.813 14.002,30.813 14.402,30.813 12.802,31.213 13.202,31.213 13.602,31.213 14.002,31.213 14.402,31.213
  other v3: 9.35,28.85 10.15,28.85 10.95,28.85 11.75,28.85 15.461,28.85 9.35,29.65 10.15,29.65 10.95,29.65 11.75,29.65 15.461,29.65 9.35,30.45 10.15,30.45 10.95,30.45 11.75,30.45 15.461,30.45 9.35,31.25 10.15,31.25 10.95,31.25 11.75,31.25 15.461,31.25
C_W2: C109.2 C114.2 L102.1 TP108.1 X3.2
  other v2: 12.802,7.95 13.202,7.95 13.602,7.95 14.002,7.95 14.402,7.95 12.802,8.35 13.202,8.35 13.602,8.35 14.002,8.35 14.402,8.35 12.802,8.75 13.202,8.75 13.602,8.75 14.002,8.75 14.402,8.75 12.802,9.15 13.202,9.15 13.602,9.15 14.002,9.15 14.402,9.15 12.802,9.55 13.202,9.55 13.602,9.55 14.002,9.55 14.402,9.55 12.802,9.95 13.202,9.95 13.602,9.95 14.002,9.95 14.402,9.95 12.802,10.35 13.202,10.35 13.602,10.35 14.002,10.35 14.402,10.35 12.802,10.75 13.202,10.75 13.602,10.75 14.002,10.75 14.402,10.75 12.802,11.15 13.202,11.15 13.602,11.15 14.002,11.15 14.402,11.15 12.802,11.55 13.202,11.55 13.602,11.55 14.002,11.55 14.402,11.55 12.802,11.95 13.202,11.95 13.602,11.95 14.002,11.95 14.402,11.95 12.802,12.35 13.202,12.35 13.602,12.35 14.002,12.35 14.402,12.35 12.802,12.75 13.202,12.75 13.602,12.75 14.002,12.75 14.402,12.75 12.802,13.15 13.202,13.15 13.602,13.15 14.002,13.15 14.402,13.15 12.802,13.55 13.202,13.55 13.602,13.55 14.002,13.55 14.402,13.55 12.802,13.95 13.202,13.95 13.602,13.95 14.002,13.95 14.402,13.95 12.802,14.35 13.202,14.35 13.602,14.35 14.002,14.35 14.402,14.35 12.802,14.75 13.202,14.75 13.602,14.75 14.002,14.75 14.402,14.75 12.802,15.15 13.202,15.15 13.602,15.15 14.002,15.15 14.402,15.15 12.802,15.55 13.202,15.55 13.602,15.55 14.002,15.55 14.402,15.55 12.802,15.95 13.202,15.95 13.602,15.95 14.002,15.95 14.402,15.95 12.802,16.35 13.202,16.35 13.602,16.35 14.002,16.35 14.402,16.35 12.802,16.75 13.202,16.75 13.602,16.75 14.002,16.75 14.402,16.75
  other v3: 16.454,14.35 16.454,15.15
C_W3: C111.2 C115.2 L103.1 TP109.1 X3.3
  other v2: 12.802,-6.513 13.202,-6.513 13.602,-6.513 14.002,-6.513 14.402,-6.513 12.802,-6.113 13.202,-6.113 13.602,-6.113 14.002,-6.113 14.402,-6.113 12.802,-5.713 13.202,-5.713 13.602,-5.713 14.002,-5.713 14.402,-5.713 12.802,-5.313 13.202,-5.313 13.602,-5.313 14.002,-5.313 14.402,-5.313 12.802,-4.913 13.202,-4.913 13.602,-4.913 14.002,-4.913 14.402,-4.913 12.802,-4.513 13.202,-4.513 13.602,-4.513 14.002,-4.513 14.402,-4.513 12.802,-4.113 13.202,-4.113 13.602,-4.113 14.002,-4.113 14.402,-4.113 12.802,-3.713 13.202,-3.713 13.602,-3.713 14.002,-3.713 14.402,-3.713 12.802,-3.313 13.202,-3.313 13.602,-3.313 14.002,-3.313 14.402,-3.313 12.802,-2.913 13.202,-2.913 13.602,-2.913 14.002,-2.913 14.402,-2.913 12.802,-2.513 13.202,-2.513 13.602,-2.513 14.002,-2.513 14.402,-2.513 12.802,-2.113 13.202,-2.113 13.602,-2.113 14.002,-2.113 14.402,-2.113 12.802,-1.713 13.202,-1.713 13.602,-1.713 14.002,-1.713 14.402,-1.713 12.802,-1.313 13.202,-1.313 13.602,-1.313 14.002,-1.313 14.402,-1.313 12.802,-0.913 13.202,-0.913 13.602,-0.913 14.002,-0.913 14.402,-0.913 12.802,-0.513 13.202,-0.513 13.602,-0.513 14.002,-0.513 14.402,-0.513 12.802,-0.113 13.202,-0.113 13.602,-0.113 14.002,-0.113 14.402,-0.113 12.802,0.287 13.202,0.287 13.602,0.287 14.002,0.287 14.402,0.287 12.802,0.687 13.202,0.687 13.602,0.687 14.002,0.687 14.402,0.687 12.802,1.087 13.202,1.087 13.602,1.087 14.002,1.087 14.402,1.087 12.802,1.487 13.202,1.487 13.602,1.487 14.002,1.487 14.402,1.487 12.802,1.887 13.202,1.887 13.602,1.887 14.002,1.887 14.402,1.887 12.802,2.287 13.202,2.287 13.602,2.287 14.002,2.287 14.402,2.287
  other v3: 10.15,-6.55 10.95,-6.55 11.75,-6.55 15.454,-6.55 10.15,-5.75 10.95,-5.75 11.75,-5.75 15.454,-5.75 10.15,-4.95 10.95,-4.95 11.75,-4.95 15.454,-4.95 10.15,-4.15 10.95,-4.15 11.75,-4.15 15.454,-4.15 10.15,-3.35 10.95,-3.35 11.75,-3.35 15.454,-3.35 11.75,-2.55 11.75,-1.75
CAN_AutoBR: S101.11 TP131.1 X102.31 | length 40.8
  Top Side w0.3: v4(36.172,-1.999) S101.11@36.172,-0.875
  Mid Layer 6 w0.2: v1(37.515,14.749) 37.515,16.251 38.515,17.251 38.515,18.937 38.803,19.225 39.197,19.225 41.075,17.347 41.075,13.612 40.275,12.812 40.275,11.468 41.161,10.582 41.161,4.468 39.767,3.075 38.81,3.075 38.065,2.33 38.065,1.689 36.172,-0.204 v4(36.172,-1.999) 40.171,-1.999 41.375,-3.203 41.375,-3.375 v1(42.5,-4.5)
  Bottom Side w0.2: v1(37.515,14.749) X102.31@39,14.75
CAN_ID1: S101.16 TP126.1 X102.33 | length 31.4
  Top Side w0.3: S101.16@29.822,-0.875 v4(29.822,0.25)
  Mid Layer 6 w0.2: v1(33.986,-3.898) 29.838,0.25 v4(29.822,0.25) 29.822,3.536 30.692,4.406 30.692,4.912 32.251,6.471 32.251,7.041 33.103,7.893 33.103,9.347 34.715,10.959 34.715,12.309 36.228,13.822 37.272,13.822 v1(39,15.55)
  Bottom Side w0.2: v1(33.986,-3.898) 33.986,-3.29 34.481,-2.795 36.225,-2.795 36.52,-2.5 TP126.1@37.75,-2.5
CAN_ID2: S101.15 TP127.1 X102.35 | length 37.6
  Top Side w0.3: S101.15@31.092,-0.875 v4(31.092,0.25)
  Mid Layer 6 w0.2: v1(39,16.35) 39.475,15.875 39.475,14.372 38.21,13.107 36.079,13.107 35.115,12.144 35.115,10.793 33.503,9.181 33.503,7.728 32.703,6.928 32.703,6.352 31.092,4.741 31.092,4.193 30.401,3.503 30.401,0.941 v4(31.092,0.25) 31.092,-0.204 37.863,-6.975 42.025,-6.975 v1(42.5,-6.5)
CAN_ID3: S101.14 TP128.1 X102.37 | length 35.8
  Top Side w0.3: S101.14@32.362,-0.875 v4(32.362,0.25)
  Mid Layer 6 w0.2: v1(39,17.15) 39.875,16.275 39.875,14.109 38.515,12.75 38.515,11.301 37.966,10.753 35.64,10.753 33.903,9.016 33.903,7.562 33.103,6.762 33.103,6.112 31.601,4.61 31.601,4.137 30.801,3.337 30.801,1.811 v4(32.362,0.25) 32.362,-0.909 37.953,-6.5 v1(40.5,-6.5)
CAN_ID4: S101.13 TP129.1 X102.39 | length 39.7
  Top Side w0.3: S101.13@33.632,-0.875 v4(33.632,0.25)
  Mid Layer 6 w0.2: v1(39,17.95) 40.275,16.675 40.275,13.944 38.915,12.584 38.915,11.136 38.132,10.353 35.806,10.353 34.303,8.85 34.303,5.615 32.446,3.757 31.787,3.757 31.201,3.171 31.201,2.089 32.441,0.85 33.032,0.85 v4(33.632,0.25) 33.632,-1.613 37.169,-5.15 38.223,-5.15 38.398,-4.975 40.697,-4.975 40.975,-4.697 40.975,-3.475 v1(40,-2.5)
CAN_ID5: S101.12 TP130.1 X102.41 | length 36.7
  Top Side w0.3: v4(34.902,-1.999) S101.12@34.902,-0.875
  Mid Layer 6 w0.2: v1(39,18.75) 40.675,17.075 40.675,13.778 39.315,12.418 39.315,10.97 38.298,9.953 35.971,9.953 34.703,8.684 34.703,5.259 32.801,3.357 31.953,3.357 31.601,3.006 31.601,2.255 32.606,1.25 33.511,1.25 34.902,-0.141 v4(34.902,-1.999) 36.403,-3.5 39.5,-3.5 v1(40.5,-4.5)
CAN_ID6: S101.9 TP133.1 X102.43 | length 32.8
  Top Side w0.3: S101.9@38.712,-0.875 v4(38.712,0.25)
  Mid Layer 6 w0.2: v1(38.45,19.566) 38.684,19.8 39.187,19.8 41.475,17.512 41.475,13.447 40.944,12.916 40.944,11.364 41.561,10.748 41.561,2.972 40.662,2.073 39.929,0.712 39.467,0.25 v4(38.712,0.25) 38.712,-0.756 39.029,-1.073 39.889,-1.073 43.316,-4.5 v1(44.5,-4.5)
DBG_SWCLK: X102.32 X104.4 | length 28.9
  Mid Layer 6 w0.2: v1(18.545,-4.12) 18.545,-3.066 19.118,-2.494 19.118,-2.173 23.248,1.957 25.384,1.957 27.24,3.813 27.24,5.118 29.886,7.764 29.886,11.705 32.931,14.75 v1(35.2,14.75)
  Bottom Side w0.2: X104.4@18.545,-4.705 v1(18.545,-4.12)
DBG_SWDIO: X102.34 X104.2 | length 30.4
  Mid Layer 6 w0.2: v1(19.518,-4.482) 19.518,-2.339 23.413,1.557 25.55,1.557 27.64,3.647 27.64,4.953 30.286,7.598 30.286,11.539 32.96,14.213 35.335,14.213 35.675,14.553 35.675,15.075 v1(35.2,15.55)
  Bottom Side w0.2: X104.2@18.945,-4.705 18.945,-4.482 v1(19.518,-4.482)
DigOUT1: R119.2 TP145.1 U102.1 U102.2 X102.27 | length 8.4
  Bottom Side w0.2: X102.27@39,13.15 39.007,13.157 40.66,13.157 41.003,13.5 TP145.1@43.533,13.5 44.5,12.935 U102.1@45.1,12.935 U102.2@45.75,12.935 R119.2@45.75,14.25
DigOUT2: R120.2 TP146.1 U103.1 U103.2 X102.29 | length 11.3
  Bottom Side w0.2: X102.29@39,13.95 40.6,13.95 43.533,16.883 TP146.1@43.533,18.855 45.735,18.855 U103.2@45.75,18.87 R120.2@45.75,20.185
